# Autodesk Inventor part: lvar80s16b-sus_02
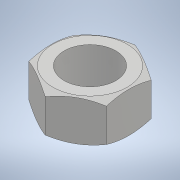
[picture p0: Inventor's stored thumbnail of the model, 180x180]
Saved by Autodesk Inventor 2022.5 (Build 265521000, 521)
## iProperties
Part Number: lvar80s16b-sus_02
Material: 一般
Document SubType Name: Modeling
Designer: ImaoCorp
Density: 1 g/cm^3
Appearance: 既定
Author: ImaoCorp
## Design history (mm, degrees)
feature "lvar80s16b-sus_02"
node "ソリッド1"
